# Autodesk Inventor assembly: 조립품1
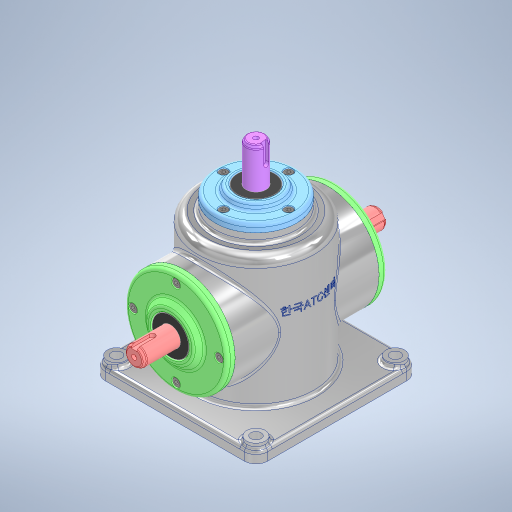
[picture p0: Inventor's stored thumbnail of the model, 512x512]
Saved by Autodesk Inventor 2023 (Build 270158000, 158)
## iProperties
Created: 2025-05
Part Number: 조립품1
Document SubType Name: Assembly
Designer: Admin
Author: Admin
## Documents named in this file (13)
- C:\Users\Admin\Desktop\750505V1004\조립품1.iam
- C:\Users\Admin\Desktop\750505V1004\본체.ipt
- C:\Users\Admin\Desktop\750505V1004\측면 커버.ipt
- C:\Users\Admin\Desktop\750505V1004\깊은 홈 볼 베어링 6203.ipt
- C:\Users\Admin\Desktop\750505V1004\오일 실 17 32 8.ipt
- C:\Users\Admin\Desktop\750505V1004\메인 축.ipt
- C:\Users\Admin\Desktop\750505V1004\평행 키 5x5.ipt
- C:\Users\Admin\Desktop\750505V1004\메인 베벨기어.ipt
- C:\Users\Admin\Desktop\750505V1004\6각 구멍붙이 볼트 M4-10L.ipt
- C:\Users\Admin\Desktop\750505V1004\윗 커버.ipt
- C:\Users\Admin\Desktop\750505V1004\서브 축.ipt
- C:\Users\Admin\Desktop\750505V1004\평행 키 4x4.ipt
- C:\Users\Admin\Desktop\750505V1004\서브 베벨기어.ipt
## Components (12 placed, 1 different names)
1. 6각 구멍붙이 볼트 M4-10L:1
2. 6각 구멍붙이 볼트 M4-10L:2
3. 6각 구멍붙이 볼트 M4-10L:3
4. 6각 구멍붙이 볼트 M4-10L:4
5. 6각 구멍붙이 볼트 M4-10L:5
6. 6각 구멍붙이 볼트 M4-10L:6
7. 6각 구멍붙이 볼트 M4-10L:7
8. 6각 구멍붙이 볼트 M4-10L:8
9. 6각 구멍붙이 볼트 M4-10L:9
10. 6각 구멍붙이 볼트 M4-10L:10
11. 6각 구멍붙이 볼트 M4-10L:11
12. 6각 구멍붙이 볼트 M4-10L:12
